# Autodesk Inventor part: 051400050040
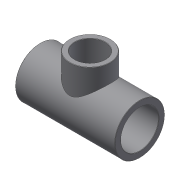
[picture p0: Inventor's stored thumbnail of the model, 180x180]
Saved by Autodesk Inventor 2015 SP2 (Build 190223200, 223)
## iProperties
Created: 2017-10
Part Number: 051400050040
Material: Generic
Description: PLASSON REDUCER TEE - CEMENT PCV 50-40-50
Document SubType Name: Modeling
Designer: KIM
Density: 1 g/cm^3
Appearance: Default
Author: KIM
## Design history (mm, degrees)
derived "051400.ipt"
feature "Solid1::051400.ipt"
feature "Solid2::051400.ipt"
tag "TaggingFeature1"
body "Solid1"
other parameters: "d0" = 118, "d1" = 61, "d2" = 31, "d5" = 45, "d7" = 0.5, "d8" = 31, "d9" = 53.5, "d12" = 36, "d23" = 26, "d24" = 0.5, "d26" = 0, "d30" = 0, "d32" = 0, "E_" = 61, "H_" = 118, "l_" = 31, "Z_" = 14, "l_1" = 26, "Z_1" = 12.5, "H_1" = 84
